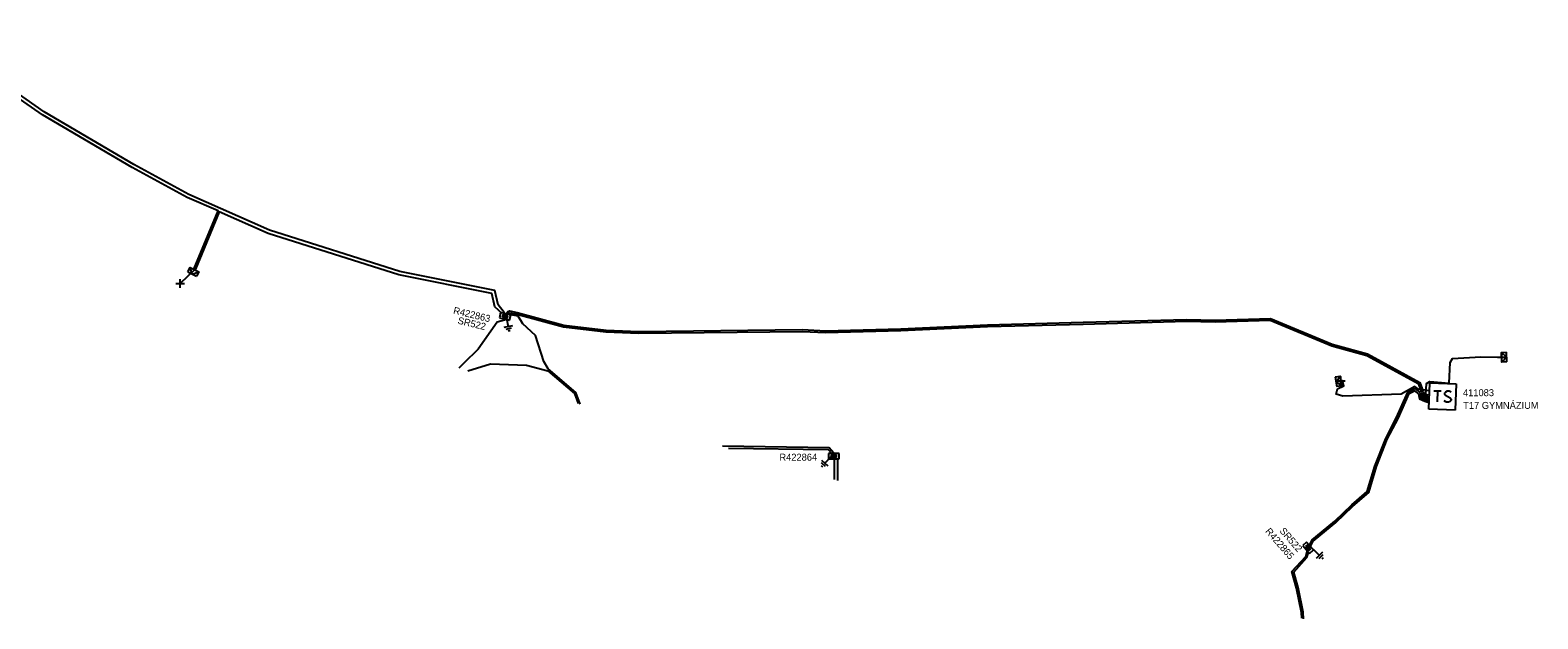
# Model space of a CAD drawing. Extents: x -540247 to -537390, y -1183887 to -1180355.
# Drawn here: x -537607.2 to -537390.3, y -1180844.9 to -1180760.2 of the extents above; entities that cross this region are included whole.
import ezdxf

# ---------------------------------------------------------------- set-up
doc = ezdxf.new("R2010")
doc.units = 0
for name, color, linetype in [('Vrstva 1', 7, 'Continuous'), ('Vrstva 14', 7, 'Continuous'), ('Vrstva 15', 7, 'Continuous'), ('Vrstva 25', 7, 'Continuous'), ('Vrstva 26', 7, 'Continuous'), ('Vrstva 27', 7, 'Continuous'), ('Vrstva 28', 7, 'Continuous'), ('Vrstva 29', 7, 'Continuous'), ('Vrstva 30', 7, 'Continuous'), ('Vrstva 31', 7, 'Continuous'), ('Vrstva 34', 7, 'Continuous'), ('Vrstva 5', 7, 'Continuous'), ('Vrstva 52', 7, 'Continuous'), ('Vrstva 59', 7, 'Continuous'), ('Vrstva 6', 7, 'Continuous'), ('Vrstva 8', 7, 'Continuous'), ('Vrstva 9', 7, 'Continuous')]:
    doc.layers.add(name, color=color, linetype=linetype)

# ---------------------------------------------------------------- blocks, each defined once
blk = doc.blocks.new('NN800')
at = {"layer": 'Vrstva 1'}
for points in [[(-0.44, 0.44), (0.44, -0.44)], [(-0.44, -0.44), (0.44, 0.44)]]:
    blk.add_lwpolyline(points, dxfattribs=at)
blk = doc.blocks.new('NN620')
at = {"layer": 'Vrstva 8'}
for points in [[(0.75, 0), (-0.75, 0)], [(-0.75, 0), (-0.75, -0.75)], [(0.75, -0.75), (0.75, 0)], [(-0.75, -0.75), (0.75, -0.75)], [(0.37, -0.18), (-0.38, -0.18)], [(-0.38, -0.18), (-0.38, -0.56)], [(-0.38, -0.56), (0.37, -0.56)], [(0.32, -0.23), (-0.33, -0.23)], [(-0.33, -0.23), (-0.33, -0.51)], [(-0.33, -0.51), (0.32, -0.51)], [(0.27, -0.27), (-0.28, -0.27)], [(-0.28, -0.27), (-0.28, -0.46)], [(-0.28, -0.46), (0.27, -0.46)], [(0.23, -0.32), (-0.23, -0.32)], [(-0.23, -0.32), (-0.23, -0.42)], [(-0.23, -0.42), (0.23, -0.42)], [(-0.19, -0.37), (0.19, -0.37)], [(0.23, -0.42), (0.23, -0.32)], [(0.27, -0.46), (0.27, -0.27)], [(0.32, -0.51), (0.32, -0.23)], [(0.37, -0.56), (0.37, -0.18)]]:
    blk.add_lwpolyline(points, dxfattribs=at)
blk = doc.blocks.new('NN630')
at = {"layer": 'Vrstva 9'}
for points in [[(0, -0.7), (-0.7, 0)], [(-0.7, -0.7), (-0.7, 0), (0.7, 0), (0.7, -0.7)], [(-0.7, -0.7), (0.7, -0.7)], [(0, -0.7), (0.7, 0)]]:
    blk.add_lwpolyline(points, dxfattribs=at)
blk = doc.blocks.new('NN810')
at = {"layer": 'Vrstva 14'}
for points in [[(0.63, -1.89), (-0.62, -1.89)], [(0, -0.64), (0, -1.89)], [(0.39, -2.2), (-0.4, -2.2)], [(0, -2.52), (-0.12, -2.52)], [(0.14, -2.52), (0, -2.52)]]:
    blk.add_lwpolyline(points, dxfattribs=at)
blk = doc.blocks.new('NN640')
at = {"layer": 'Vrstva 6'}
for points in [[(-1.89, 1.89), (1.89, 1.89)], [(-1.89, -1.89), (-1.89, 1.89)], [(-1.26, 0.79), (-0.22, 0.79)], [(-0.73, 0.79), (-0.73, -0.79)], [(1.2, 0.66), (0.94, 0.79), (0.66, 0.79), (0.41, 0.66), (0.28, 0.47), (0.28, 0.41), (0.41, 0.22), (1.13, -0.16), (1.26, -0.32), (1.26, -0.47), (1.13, -0.66), (0.91, -0.79), (0.63, -0.79), (0.5, -0.73), (0.28, -0.6)], [(1.89, 1.89), (1.89, -1.89)], [(1.89, -1.89), (-1.89, -1.89)]]:
    blk.add_lwpolyline(points, dxfattribs=at)

msp = doc.modelspace()

# ---------------------------------------------------------------- linework, layer by layer
at = {"layer": 'Vrstva 5'}
for points in [[(-537539.27, -1180800.97), (-537540.33, -1180800.01), (-537540.77, -1180798.09), (-537554.14, -1180795.43), (-537572.94, -1180789.46), (-537579.99, -1180786.34), (-537583.4, -1180794.6), (-537583.56, -1180794.69), (-537583.6, -1180794.52), (-537580.17, -1180786.23), (-537584.61, -1180784.3), (-537592.51, -1180779.99), (-537605.42, -1180772.39), (-537614.61, -1180766.01), (-537620.35, -1180761.52), (-537621.15, -1180761.13), (-537621.78, -1180760.86), (-537622.41, -1180760.33)], [(-537539, -1180801.01), (-537538.98, -1180800.82), (-537539.87, -1180799.75), (-537540.35, -1180797.67), (-537554.02, -1180794.95), (-537572.76, -1180789), (-537584.39, -1180783.86), (-537592.27, -1180779.55), (-537605.16, -1180771.97), (-537614.31, -1180765.61), (-537620.03, -1180761.14), (-537621, -1180760.93), (-537621.67, -1180760.69), (-537622.25, -1180760.23)], [(-537538.91, -1180801.8), (-537538.94, -1180801.96), (-537540, -1180802.24), (-537542.72, -1180806.12), (-537544.8, -1180808.13), (-537545.5, -1180808.83)], [(-537538.74, -1180801.06), (-537538.46, -1180800.72), (-537538.21, -1180800.61), (-537537.13, -1180800.82), (-537530.39, -1180802.67), (-537524.33, -1180803.38), (-537519.64, -1180803.57), (-537496.09, -1180803.31), (-537492.78, -1180803.49), (-537481.94, -1180803.2), (-537469.47, -1180802.6), (-537455.67, -1180802.25), (-537440.83, -1180801.84), (-537436.67, -1180801.93), (-537428.72, -1180801.69), (-537419.84, -1180805.4), (-537414.79, -1180806.81), (-537407.24, -1180810.9), (-537406.74, -1180812.23), (-537406.65, -1180812.75), (-537406.29, -1180812.9), (-537405.94, -1180812.99)], [(-537538.48, -1180801.12), (-537538.32, -1180800.94), (-537538.18, -1180800.88), (-537537.19, -1180801.07), (-537530.44, -1180802.91), (-537524.35, -1180803.62), (-537519.64, -1180803.82), (-537496.09, -1180803.56), (-537492.78, -1180803.74), (-537481.93, -1180803.45), (-537469.47, -1180802.85), (-537455.67, -1180802.5), (-537440.83, -1180802.09), (-537436.67, -1180802.18), (-537428.76, -1180801.95), (-537419.92, -1180805.64), (-537414.89, -1180807.05), (-537407.46, -1180811.06), (-537406.99, -1180812.28), (-537406.87, -1180812.92), (-537406.37, -1180813.14), (-537405.95, -1180813.25)], [(-537528.04, -1180814.02), (-537528.66, -1180812.33), (-537532.65, -1180808.97), (-537533.31, -1180807.91), (-537534.5, -1180804.16), (-537536.29, -1180802.47), (-537537, -1180801.36), (-537538.23, -1180801.12), (-537538.29, -1180801.16)], [(-537544.2, -1180809.22), (-537540.94, -1180808.21), (-537535.77, -1180808.4), (-537532.72, -1180809.25), (-537528.88, -1180812.49), (-537528.34, -1180813.93)], [(-537423.1, -1180834.34), (-537422.74, -1180833.56), (-537419.49, -1180830.86), (-537417.03, -1180828.53), (-537414.82, -1180826.59), (-537413.73, -1180822.93), (-537412.14, -1180818.96), (-537410.59, -1180815.97), (-537408.96, -1180812.31), (-537407.98, -1180811.79), (-537407.23, -1180812.3), (-537407.09, -1180813.1), (-537406.45, -1180813.38), (-537406.04, -1180813.49), (-537405.96, -1180813.49)], [(-537422.95, -1180834.52), (-537422.58, -1180833.76), (-537419.33, -1180831.04), (-537416.87, -1180828.71), (-537414.6, -1180826.73), (-537413.49, -1180823.01), (-537411.92, -1180819.06), (-537410.37, -1180816.07), (-537408.76, -1180812.49), (-537408.02, -1180812.1), (-537407.43, -1180812.52), (-537407.31, -1180813.27), (-537406.53, -1180813.62), (-537406.07, -1180813.73), (-537405.96, -1180813.74)], [(-537491.58, -1180821.1), (-537492.25, -1180820.32), (-537507.59, -1180820.09)], [(-537506.7, -1180820.35), (-537492.37, -1180820.56), (-537491.91, -1180821.1)], [(-537424.22, -1180844.84), (-537424.28, -1180844), (-537424.97, -1180840.48), (-537425.64, -1180838.12), (-537423.66, -1180835.95), (-537423.45, -1180835.16)], [(-537423.96, -1180844.91), (-537424.04, -1180843.96), (-537424.73, -1180840.42), (-537425.36, -1180838.18), (-537423.48, -1180836.11), (-537423.27, -1180835.37)]]:
    msp.add_lwpolyline(points, dxfattribs=at)
at = {"layer": 'Vrstva 52'}
for points in [[(-537405.94, -1180812.74), (-537406.37, -1180812.62), (-537406.28, -1180811.04), (-537405.82, -1180810.75), (-537403, -1180810.99), (-537402.87, -1180808.04), (-537402.53, -1180807.48), (-537398.45, -1180807.23), (-537395.46, -1180807.29)], [(-537405.87, -1180812.11), (-537407.42, -1180811.87), (-537407.97, -1180811.49), (-537409.95, -1180812.57), (-537418.31, -1180812.86), (-537419.28, -1180812.59), (-537419.07, -1180811.84), (-537418.19, -1180811.39), (-537418.39, -1180810.67), (-537418.61, -1180810.69)]]:
    msp.add_lwpolyline(points, dxfattribs=at)
at = {"layer": 'Vrstva 59'}
for points in [[(-537583.56, -1180794.69), (-537585.62, -1180796.66)], [(-537491.49, -1180821.85), (-537491.5, -1180824.86)], [(-537491.02, -1180821.86), (-537491.02, -1180825.01)]]:
    msp.add_lwpolyline(points, dxfattribs=at)

# ---------------------------------------------------------------- block references
at = {"layer": 'Vrstva 15'}
for p, rotation in [((-537538.78, -1180801.03), 11.175980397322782), ((-537491.56, -1180821.13), -42.231711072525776), ((-537423.04, -1180834.44), 44.99999995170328)]:
    msp.add_blockref('NN810', p, dxfattribs=dict(at, rotation=rotation))
at = {"layer": 'Vrstva 25', "rotation": -2.259422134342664}
msp.add_blockref('NN640', (-537403.98, -1180812.93), dxfattribs=at)
at = {"layer": 'Vrstva 28'}
for p, rotation in [((-537538.78, -1180801.04), -13.436633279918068), ((-537423.04, -1180834.44), -49.09191936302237)]:
    msp.add_blockref('NN620', p, dxfattribs=dict(at, rotation=rotation))
msp.add_blockref('NN620', (-537491.56, -1180821.13), dxfattribs=at)
at = {"layer": 'Vrstva 31'}
for p, rotation in [((-537583.56, -1180794.69), -26.352230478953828), ((-537395.46, -1180807.29), 92.26042230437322), ((-537418.61, -1180810.69), -80.60970000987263)]:
    msp.add_blockref('NN630', p, dxfattribs=dict(at, rotation=rotation))
at = {"layer": 'Vrstva 34', "rotation": 45}
for p in [(-537585.62, -1180796.66), (-537395.46, -1180807.29), (-537418.61, -1180810.69)]:
    msp.add_blockref('NN800', p, dxfattribs=at)

# ---------------------------------------------------------------- texts
at = {"layer": 'Vrstva 26'}
msp.add_text('411083', height=1, dxfattribs=at).set_placement((-537401.03, -1180812.88))
at = {"layer": 'Vrstva 27'}
msp.add_text('T17 GYMNÁZIUM', height=1, rotation=0.066, dxfattribs=at).set_placement((-537401, -1180814.71))
at = {"layer": 'Vrstva 29'}
for s, rotation, p in [('R422863', 346.563, (-537546.39, -1180800.99)), ('R422865', 310.908, (-537429.54, -1180832.36))]:
    msp.add_text(s, height=1, rotation=rotation, dxfattribs=at).set_placement(p)
msp.add_text('R422864', height=1, dxfattribs=at).set_placement((-537499.39, -1180822.16))
at = {"layer": 'Vrstva 30'}
for rotation, p in [(346.563, (-537545.75, -1180802.44)), (310.908, (-537427.49, -1180832.31))]:
    msp.add_text('SR522', height=1, rotation=rotation, dxfattribs=at).set_placement(p)

doc.saveas('drawing.dxf')
